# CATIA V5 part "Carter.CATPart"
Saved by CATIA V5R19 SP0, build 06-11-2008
Part number: Carter
Bounding box of the stored display mesh (mm): x -55 to 55, y -55 to 55, z -40 to 20
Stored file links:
  F:\IAO\Catia\Carter.CATPart
  F:\IAO\Catia\Etau.CATProduct
  F:\IAO\Catia\Base.CATPart
  F:\IAO\Catia\Barre1.CATPart
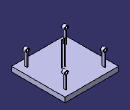
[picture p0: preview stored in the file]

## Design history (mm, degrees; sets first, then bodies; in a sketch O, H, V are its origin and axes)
Set1
  Plane1: linked copy from another document
  Point1: linked copy from another document
  Point2: linked copy from another document
  Plane2: linked copy from another document
  Point3: linked copy from another document
  Point4: linked copy from another document
Body1 (main body)
  Sketch1 on Plane1, origin (0, 0, -30), H (1, 0, 0), V (0, 1, 0)
    line L1 (0, 0) -> (55, 0)
    line L2 (55, 0) -> (55, 55)
    line L3 (55, 55) -> (0, 55)
    line L4 (0, 55) -> (0, 0)
    reference projected point E1 (40, 40) from Point1
    reference projected point E2 (40, 40) from Point1
    distance E1 L3 = 15
    distance E2 L2 = 15
    horizontal: L1 H, L3 H
    vertical: L2 V, L4 V
  Pad1: profile Sketch1, direction (0, 0, -1), length 10
  CircPattern1: of Pad1, instances 4, angular step 90, axis from Z axis
  Sketch2 on Plane2, origin (0, -40, 0), H (-1, 0, 0), V (0, 0, 1)
    arc A1 centre (40, 0) radius 4 from (41, -3.873) to (39, -3.873) ccw
    point P1 (40, 0)
    reference projected point E1 (40, 0) from Point3
    line L1 (39, -30.873) -> (41, -30.873)
    line L2 (41, -30.873) -> (41, -3.873)
    line L3 (39, -3.873) -> (39, -30.873)
    point P5 (39, -3.873)
    point P6 (39, -3.873)
    circle A2 centre (40, 0) radius 2.5
    point P7 (40, 0)
    reference projected point E2 (40, 0) from Point3
    length L2 = 27
    length L3 = 27
    radius A1 = 4
    length L1 = 2
    radius A2 = 2.5
    coincidence: P1 H, P1 E1, L3 P6, P6 P5, P7 H, P7 E2
    horizontal: L1 H
    vertical: L2 V, L3 V
  Pad2: profile Sketch2, direction (0, 1, 0), length 3, mirrored extent
  RectPattern1: of Pad2, direction 1 instances 2, spacing 80, along xy-plane, direction 2 instances 2, spacing 80, along xy-plane
  Plane3: stored without definition
  Sketch3 on face of CircPattern1, origin (0, 0, -30), H (1, 0, 0), V (0, 1, 0)
    point P1 (23.246, 0)
    circle A1 centre (6, 0) radius 1
    point P2 (6, 0)
    circle A2 centre (0, 0) radius 1
    point P3 (0, 0)
    reference projected point E1 (0, 0) from Point2
    reference projected point E2 (6, 0) from Point4
    radius A2 = 1
    radius A1 = 1
    coincidence: P3 E1, P2 E2
  Pad3: profile Sketch3, direction (0, 0, 1), length 50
